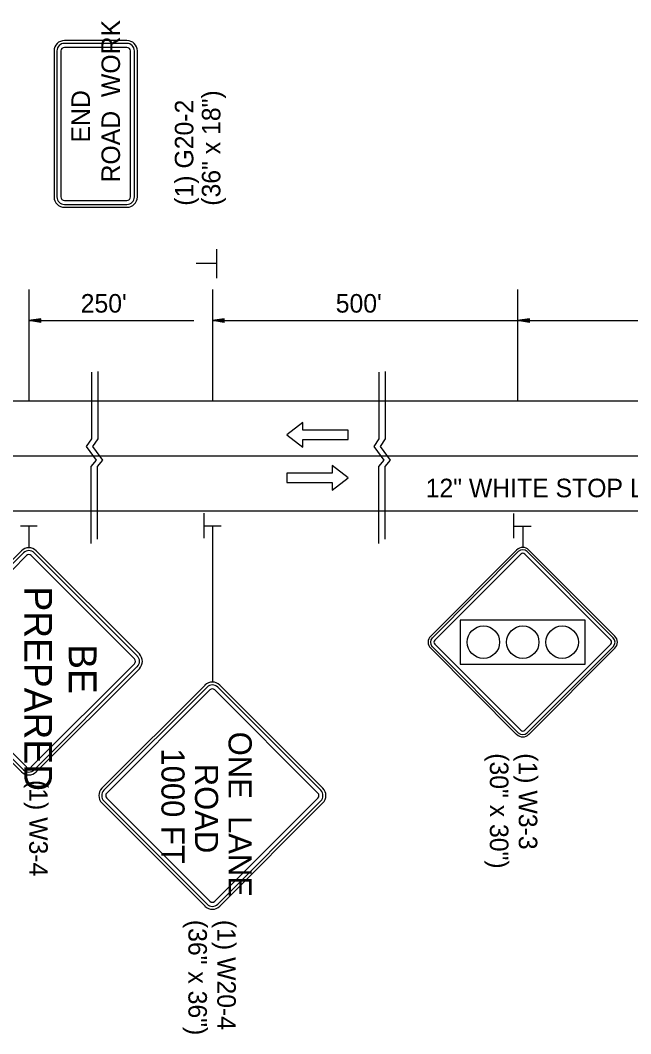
# Model space of a CAD drawing. Extents: x 1927831 to 1930787, y 596452 to 597699.
# Drawn here: x 1928342.4 to 1928540.2, y 597300.7 to 597628.8 of the extents above; entities that cross this region are included whole.
import ezdxf

# ---------------------------------------------------------------- set-up
doc = ezdxf.new("R2010")
doc.units = 0
for name, color, linetype in [('Default', 7, 'Continuous'), ('P_TC_Signs_Permanent', 7, 'Continuous'), ('P_TC_Signs_Temporary', 7, 'Continuous'), ('R_Border', 7, 'Continuous'), ('R_Striping', 7, 'Continuous')]:
    doc.layers.add(name, color=color, linetype=linetype)

msp = doc.modelspace()

# ---------------------------------------------------------------- linework, layer by layer
at = {"layer": 'Default'}
for p, q in [((1928406.01, 597554.74), (1928406.01, 597545.26)), ((1928405.87, 597550.02), (1928399.4, 597550.02)), ((1928345.2, 597541.61), (1928345.2, 597505.58)), ((1928404.65, 597541.61), (1928404.65, 597505.58)), ((1928503.55, 597541.61), (1928503.55, 597505.58)), ((1928349.04, 597532.14), (1928345.2, 597531.57)), ((1928345.2, 597531.57), (1928398.6, 597531.57)), ((1928349.04, 597530.99), (1928345.2, 597531.57)), ((1928349.04, 597532.05), (1928345.84, 597531.57)), ((1928349.04, 597531.09), (1928345.84, 597531.57)), ((1928349.04, 597531.95), (1928346.5, 597531.57)), ((1928349.04, 597531.18), (1928346.5, 597531.57)), ((1928349.04, 597531.85), (1928347.14, 597531.57)), ((1928349.04, 597531.28), (1928347.14, 597531.57)), ((1928349.04, 597531.75), (1928347.79, 597531.57)), ((1928349.04, 597531.38), (1928347.79, 597531.57)), ((1928349.04, 597531.66), (1928348.43, 597531.57)), ((1928349.04, 597531.48), (1928348.43, 597531.57)), ((1928349.04, 597530.99), (1928349.04, 597532.14)), ((1928408.49, 597532.14), (1928404.65, 597531.57)), ((1928404.65, 597531.57), (1928504.41, 597531.57)), ((1928408.49, 597530.99), (1928404.65, 597531.57)), ((1928408.49, 597532.05), (1928405.3, 597531.57)), ((1928408.49, 597531.09), (1928405.3, 597531.57)), ((1928408.49, 597531.95), (1928405.96, 597531.57)), ((1928408.49, 597531.18), (1928405.96, 597531.57)), ((1928408.49, 597531.85), (1928406.59, 597531.57)), ((1928408.49, 597531.28), (1928406.59, 597531.57)), ((1928408.49, 597531.75), (1928407.24, 597531.57)), ((1928408.49, 597531.38), (1928407.24, 597531.57)), ((1928408.49, 597531.66), (1928407.89, 597531.57)), ((1928408.49, 597531.48), (1928407.89, 597531.57)), ((1928408.49, 597530.99), (1928408.49, 597532.14)), ((1928507.39, 597532.14), (1928503.55, 597531.57)), ((1928503.55, 597531.57), (1928604.69, 597531.57)), ((1928507.39, 597530.99), (1928503.55, 597531.57)), ((1928507.39, 597532.05), (1928504.2, 597531.57)), ((1928507.39, 597531.09), (1928504.2, 597531.57)), ((1928507.39, 597531.95), (1928504.86, 597531.57)), ((1928507.39, 597531.18), (1928504.86, 597531.57)), ((1928507.39, 597531.85), (1928505.49, 597531.57)), ((1928507.39, 597531.28), (1928505.49, 597531.57)), ((1928507.39, 597531.75), (1928506.14, 597531.57)), ((1928507.39, 597531.38), (1928506.14, 597531.57)), ((1928507.39, 597531.66), (1928506.79, 597531.57)), ((1928507.39, 597531.48), (1928506.79, 597531.57)), ((1928507.39, 597530.99), (1928507.39, 597532.14)), ((1928044.85, 597505.58), (1929173.7, 597505.58)), ((1927908.3, 597487.79), (1929173.7, 597487.79)), ((1928044.85, 597470), (1929173.7, 597470)), ((1928401.98, 597461.2), (1928401.98, 597469.2)), ((1928502.38, 597461.1), (1928502.38, 597469.1)), ((1928342.47, 597465.18), (1928347.93, 597465.18)), ((1928402.1, 597465.18), (1928407.56, 597465.18)), ((1928502.49, 597465.08), (1928507.96, 597465.08))]:
    msp.add_line(p, q, dxfattribs=at)
for points in [[(1928365.46, 597514.86), (1928365.46, 597493.34), (1928363.8, 597490.87), (1928367.04, 597486.44), (1928365.33, 597484.39), (1928365.33, 597459.37)], [(1928367.5, 597515.06), (1928367.5, 597493.25), (1928365.84, 597490.78), (1928369.08, 597486.35), (1928367.38, 597484.31), (1928367.37, 597460.81)], [(1928458.63, 597514.86), (1928458.63, 597493.34), (1928456.96, 597490.87), (1928460.2, 597486.44), (1928458.5, 597484.39), (1928458.49, 597459.37)], [(1928460.67, 597515.06), (1928460.67, 597493.25), (1928459.01, 597490.78), (1928462.25, 597486.35), (1928460.54, 597484.31), (1928460.54, 597460.81)]]:
    msp.add_lwpolyline(points, dxfattribs=at)
at = {"layer": 'P_TC_Signs_Permanent'}
for p, q in [((1928342.81, 597457.08), (1928309.4, 597423.67)), ((1928381, 597423.67), (1928347.59, 597457.08)), ((1928475.4, 597429.47), (1928503.24, 597457.31)), ((1928507.22, 597457.31), (1928535.06, 597429.47)), ((1928343.48, 597456.42), (1928310.07, 597423.01)), ((1928344.41, 597455.49), (1928310.99, 597422.08)), ((1928379.41, 597422.08), (1928346, 597455.49)), ((1928380.34, 597423.01), (1928346.92, 597456.42)), ((1928475.93, 597428.94), (1928503.77, 597456.78)), ((1928504.56, 597455.99), (1928476.72, 597428.15)), ((1928533.73, 597428.15), (1928505.89, 597455.99)), ((1928506.69, 597456.78), (1928534.53, 597428.94)), ((1928503.24, 597397.65), (1928475.4, 597425.49)), ((1928503.77, 597398.18), (1928475.93, 597426.02)), ((1928476.72, 597426.82), (1928504.56, 597398.98)), ((1928505.89, 597398.98), (1928533.73, 597426.82)), ((1928534.53, 597426.02), (1928506.69, 597398.18)), ((1928535.06, 597425.49), (1928507.22, 597397.65)), ((1928309.4, 597418.89), (1928342.81, 597385.48)), ((1928310.07, 597419.56), (1928343.48, 597386.15)), ((1928310.99, 597420.49), (1928344.41, 597387.08)), ((1928346, 597387.08), (1928379.41, 597420.49)), ((1928346.92, 597386.15), (1928380.34, 597419.56)), ((1928347.59, 597385.48), (1928381, 597418.89))]:
    msp.add_line(p, q, dxfattribs=at)
msp.add_lwpolyline([(1928484.98, 597434.61), (1928484.98, 597420.36), (1928525.48, 597420.36), (1928525.48, 597434.61)], close=True, dxfattribs=at)
for centre in [(1928492.48, 597427.48), (1928505.23, 597427.48), (1928517.98, 597427.48)]:
    msp.add_circle(centre, 5.25, dxfattribs=at)
for centre, radius, start, end in [((1928345.2, 597454.69), 3.37, 45, 135), ((1928345.2, 597454.69), 2.44, 45, 135), ((1928505.23, 597455.33), 2.81, 45, 135), ((1928505.23, 597455.33), 2.06, 45, 135), ((1928345.2, 597454.69), 1.13, 45, 135), ((1928505.23, 597455.33), 0.938, 45, 135), ((1928477.38, 597427.48), 2.81, 135, 225), ((1928477.38, 597427.48), 2.06, 135, 225), ((1928477.38, 597427.48), 0.938, 135, 225), ((1928533.07, 597427.48), 0.938, 315, 45), ((1928533.07, 597427.48), 2.06, 315, 45), ((1928533.07, 597427.48), 2.81, 315, 45), ((1928378.61, 597421.28), 1.13, 315, 45), ((1928378.61, 597421.28), 2.44, 315, 45), ((1928378.61, 597421.28), 3.37, 315, 45), ((1928505.23, 597399.64), 2.06, 225, 315), ((1928505.23, 597399.64), 0.938, 225, 315), ((1928505.23, 597399.64), 2.81, 225, 315), ((1928345.2, 597387.87), 3.37, 225, 315), ((1928345.2, 597387.87), 2.44, 225, 315), ((1928345.2, 597387.87), 1.13, 225, 315)]:
    msp.add_arc(centre, radius, start, end, dxfattribs=at)
at = {"layer": 'P_TC_Signs_Temporary'}
for p, q in [((1928376.98, 597622.24), (1928356.73, 597622.24)), ((1928376.98, 597621.3), (1928356.73, 597621.3)), ((1928353.35, 597618.86), (1928353.35, 597571.61)), ((1928354.29, 597618.86), (1928354.29, 597571.61)), ((1928355.6, 597618.86), (1928355.6, 597571.61)), ((1928376.98, 597619.99), (1928356.73, 597619.99)), ((1928378.1, 597571.61), (1928378.1, 597618.86)), ((1928379.41, 597571.61), (1928379.41, 597618.86)), ((1928380.35, 597571.61), (1928380.35, 597618.86)), ((1928356.73, 597570.49), (1928376.98, 597570.49)), ((1928356.73, 597569.17), (1928376.98, 597569.17)), ((1928356.73, 597568.24), (1928376.98, 597568.24)), ((1928368.86, 597380.2), (1928402.27, 597413.61)), ((1928369.52, 597379.54), (1928402.93, 597412.95)), ((1928370.45, 597378.61), (1928403.86, 597412.02)), ((1928405.45, 597412.02), (1928438.86, 597378.61)), ((1928406.38, 597412.95), (1928439.79, 597379.54)), ((1928407.04, 597413.61), (1928440.45, 597380.2)), ((1928402.27, 597342.02), (1928368.86, 597375.43)), ((1928402.93, 597342.68), (1928369.52, 597376.09)), ((1928403.86, 597343.61), (1928370.45, 597377.02)), ((1928438.86, 597377.02), (1928405.45, 597343.61)), ((1928439.79, 597376.09), (1928406.38, 597342.68)), ((1928440.45, 597375.43), (1928407.04, 597342.02))]:
    msp.add_line(p, q, dxfattribs=at)
for centre, radius, start, end in [((1928356.73, 597618.86), 3.37, 90, 180), ((1928356.73, 597618.86), 2.44, 90, 180), ((1928376.98, 597618.86), 3.37, 360, 90), ((1928376.98, 597618.86), 2.44, 360, 90), ((1928356.73, 597618.86), 1.13, 90, 180), ((1928376.98, 597618.86), 1.13, 360, 90), ((1928356.73, 597571.61), 3.37, 180, 270), ((1928356.73, 597571.61), 2.44, 180, 270), ((1928356.73, 597571.61), 1.13, 180, 270), ((1928376.98, 597571.61), 2.44, 270, 360), ((1928376.98, 597571.61), 1.13, 270, 360), ((1928376.98, 597571.61), 3.37, 270, 360), ((1928404.65, 597411.22), 3.37, 45, 135), ((1928404.65, 597411.22), 2.44, 45, 135), ((1928404.65, 597411.22), 1.12, 45, 135), ((1928371.24, 597377.81), 3.37, 135, 225), ((1928371.24, 597377.81), 2.44, 135, 225), ((1928371.24, 597377.81), 1.13, 135, 225), ((1928438.06, 597377.81), 1.13, 315, 45), ((1928438.06, 597377.81), 2.44, 315, 45), ((1928438.06, 597377.81), 3.37, 315, 45), ((1928404.65, 597344.4), 2.44, 225, 315), ((1928404.65, 597344.4), 1.12, 225, 315), ((1928404.65, 597344.4), 3.37, 225, 315)]:
    msp.add_arc(centre, radius, start, end, dxfattribs=at)
at = {"layer": 'R_Border'}
for p, q in [((1928345.2, 597465.18), (1928345.2, 597458.07)), ((1928404.65, 597465.18), (1928404.65, 597414.6)), ((1928505.23, 597465.08), (1928505.23, 597458.14))]:
    msp.add_line(p, q, dxfattribs=at)
at = {"layer": 'R_Striping'}
for points in [[(1928433.95, 597498.63), (1928428.75, 597494.63), (1928433.95, 597490.63), (1928433.95, 597493.13), (1928448.66, 597493.13), (1928448.66, 597496.13), (1928433.95, 597496.13)], [(1928443.47, 597476.68), (1928448.66, 597480.68), (1928443.47, 597484.68), (1928443.47, 597482.18), (1928428.75, 597482.18), (1928428.75, 597479.18), (1928443.47, 597479.18)]]:
    msp.add_lwpolyline(points, close=True, dxfattribs=at)

# ---------------------------------------------------------------- texts
at = {"layer": 'Default'}
for s, p in [("250'", (1928362, 597534.16)), ("500'", (1928444.63, 597534.16)), ('12" WHITE STOP LINE', (1928473.77, 597474.39))]:
    msp.add_text(s, height=6, rotation=360, dxfattribs=at).set_placement(p)
at = {"layer": 'P_TC_Signs_Temporary'}
for s, height, rotation, p in [('ROAD  WORK', 6, 90, (1928374.73, 597576.28)), ('END', 6, 90, (1928364.98, 597589.21)), ('PREPARED', 9, 270, (1928343.73, 597445.52)), ('BE', 9, 270, (1928358.13, 597426.83)), ('ONE  LANE', 7.5, 270, (1928409.9, 597398.51)), ('1000 FT', 7.5, 270, (1928388.15, 597393.1)), ('ROAD', 7.5, 270, (1928399.03, 597388.12))]:
    msp.add_text(s, height=height, rotation=rotation, dxfattribs=at).set_placement(p)
at = {"layer": 'R_Border'}
for s, height, rotation, p in [('(36" x 18")', 5.9996, 90, (1928407.25, 597568.75)), ('(1) G20-2', 6, 90, (1928398.5, 597568.75)), ('(30" x 30")', 5.9996, 270, (1928494.57, 597391.54)), ('(1) W3-3', 6, 270, (1928503.93, 597391.54)), ('(1) W3-4', 6, 270, (1928345.33, 597382.88)), ('(36" x 36")', 5.9996, 270, (1928396.89, 597337.6)), ('(1) W20-4', 6, 270, (1928406.25, 597337.6))]:
    msp.add_text(s, height=height, rotation=rotation, dxfattribs=at).set_placement(p)

doc.saveas('drawing.dxf')
